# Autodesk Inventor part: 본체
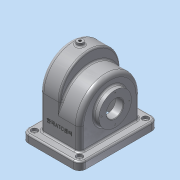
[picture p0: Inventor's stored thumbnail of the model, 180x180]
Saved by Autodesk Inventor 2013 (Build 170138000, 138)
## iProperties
Created: 2017-11
Part Number: 본체
Material: 알루미늄 6061
Document SubType Name: Modeling
Designer: dgall
Density: 2.71 g/cm^3
Mass: 1079.37 g
Surface Area: 1182.18 cm^2
Volume: 398.29 cm^3
Author: dgall
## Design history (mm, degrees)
sketch "스케치1"
  geometry: L1 (-38, -58)-(38, -58); L2 (38, -58)-(38, 58); L3 (38, 58)-(-38, 58); L4 (-38, 58)-(-38, -58); L5 (-38, -58)-(38, 58); L6 (38, -58)-(-38, 58); 1 further point
  constraints: 12 end point, 2 midpoint, 2 parallel, 1 horizontal, 1 perpendicular
  dimensions: "d0" = 76 distance of L3.end L2.end; "d1" = 116 distance between parallel lines of L1 L3
extrude "돌출1" new body sketch "스케치1" distance "d2" = 138; taper "d3" = 0 deg
node "작업 평면1"
sketch "스케치2"
  geometry: L1 (-58, 0)-(-58, 138) reference; L2 (58, 0)-(58, 138) reference; L3 (58, 0)-(-58, 0) reference; L4 (58, 138)-(-58, 138) reference; L5 (-58, 57)-(-58, 138); L6 (58, 138)-(-58, 138); L7 (58, 138)-(58, 57); A1 r 58 centre (0, 57) between (58, 57) and (-58, 57); 1 further point
  constraints: 6 end point, 2 collinear, 2 point on circle, 2 point on line, 1 centre point, 1 perpendicular, 1 vertical alignment
  dimensions: "d5" = 57 distance of point (0, 0) A1.centre; "d6" = 116 diameter of A1
extrude "돌출2" cut sketch "스케치2" stored distance "d7" = 138; taper "d8" = 0 deg
fillet "모깎기1" dims "d9" = 58
feature "쉘3" dims "d19" = 5
fillet "모깎기5" dims "d21" = 8
fillet "모깎기6" dims "d22" = 3
fillet "모깎기7" dims "d23" = 3
sketch "스케치4"
  geometry: L1 (0, 0)-(0, 100) reference; C1 r 31 at (-65, 50); 2 further points
  constraints: 1 centre point, 1 horizontal alignment, 1 midpoint
  dimensions: "d25" = 62 diameter of C1; "d27" = 65 distance of C1.centre point (0, 50)
extrude "돌출3" join sketch "스케치4" distance "d28" = 10; taper "d29" = 0 deg
sketch "스케치5"
  geometry: C1 r 31 at (0, 0) reference; C2 r 16 at (0, 0); 1 further point
  constraints: 1 centre point, 1 coincident
  dimensions: "d30" = 32 diameter of C2
extrude "돌출4" cut sketch "스케치5" stored distance "d32" = 10; taper "d33" = 0 deg
sketch "스케치6"
  geometry: C1 r 16 at (65, 50) reference; C2 r 37.5 at (65, 50); 1 further point
  constraints: 1 centre point, 1 coincident
  dimensions: "d34" = 75 diameter of C2
extrude "돌출5" join sketch "스케치6" distance "d35" = 9; taper "d36" = 0 deg
chamfer "모따기1" distance "d37" = 1; stored, may be unused: second distance "d38" = 2, angle "d39" = 45 deg
fillet "모깎기8" dims "d40" = 3
node "작업 평면8"
sketch "스케치7"
  geometry: L1 (-38, -50)-(-38, 50) reference; C1 r 6 at (-19, 0); 1 further point
  constraints: 1 centre point, 1 horizontal alignment
  dimensions: "d42" = 12 diameter of C1; "d44" = 19 distance from line of L1 C1.centre
extrude "돌출6" join sketch "스케치7" stored distance "d45" = 12 (= d42); taper "d46" = 0 deg
sketch "스케치8"
  geometry: C1 r 6 at (0, 0) reference; C2 r 2.5 at (0, 0); 1 further point
  constraints: 1 centre point, 1 coincident
  dimensions: "d47" = 5 diameter of C2
extrude "돌출7" cut sketch "스케치8" stored distance "d48" = 9; taper "d49" = 0 deg
feature "스레드1" dims "d50" = 10, "d51" = 0
fillet "모깎기9" dims "d52" = 3
sketch "스케치9"
  geometry: L1 (-38, -50)-(-38, 50) reference; L2 (30, -58)-(-30, -58) reference; L3 (38, 50)-(38, -50) reference; L4 (-30, 58)-(30, 58) reference; L5 (-55, -75)-(55, -75); L6 (55, -75)-(55, 75); L7 (55, 75)-(-55, 75); L8 (-55, 75)-(-55, -75); L9 (-55, -75)-(55, 75); L10 (55, -75)-(-55, 75); A1 r 8 centre (-30, 50) between (-30, 58) and (-38, 50) reference; A2 r 8 centre (-30, -50) between (-38, -50) and (-30, -58) reference; A3 r 8 centre (30, -50) between (30, -58) and (38, -50) reference; A4 r 8 centre (30, 50) between (38, 50) and (30, 58) reference; 1 further point
  constraints: 12 end point, 2 midpoint, 2 parallel, 1 horizontal, 1 perpendicular
  dimensions: "d53" = 110 distance of L7.end L6.end; "d54" = 150 distance of L6.end L5.end
extrude "돌출8" join sketch "스케치9" distance "d55" = 15; taper "d56" = 0 deg
fillet "모깎기10" dims "d57" = 12
fillet "모깎기11" dims "d58" = 3
fillet "모깎기12" dims "d59" = 3
sketch "스케치10"
  geometry: C1 r 2.5 at (43, -63); C2 r 2.5 at (43, 63); C3 r 2.5 at (-43, 63); C4 r 2.5 at (-43, -63); A1 r 9 centre (43, 63) between (52, 63) and (43, 72) reference; A2 r 9 centre (-43, 63) between (-43, 72) and (-52, 63) reference; A3 r 9 centre (-43, -63) between (-52, -63) and (-43, -72) reference; A4 r 9 centre (43, -63) between (43, -72) and (52, -63) reference; 1 further point
  constraints: 4 centre point, 4 coincident, 3 equal radius
  dimensions: "d61" = 5 diameter of C1
extrude "돌출9" cut sketch "스케치10" stored distance "d63" = 15; taper "d64" = 0 deg
sketch "스케치11"
  geometry: C1 r 2.5 at (-43, 63) reference; C2 r 2.5 at (43, -63) reference; C3 r 2.5 at (43, 63) reference; C4 r 2.5 at (-43, -63) reference; C5 r 6 at (43, -63); C6 r 6 at (43, 63); C7 r 6 at (-43, 63); C8 r 6 at (-43, -63); A1 r 9 centre (43, 63) between (52, 63) and (43, 72) reference; A2 r 9 centre (-43, 63) between (-43, 72) and (-52, 63) reference; A3 r 9 centre (-43, -63) between (-52, -63) and (-43, -72) reference; A4 r 9 centre (43, -63) between (43, -72) and (52, -63) reference; 1 further point
  constraints: 4 centre point, 4 coincident, 1 equal radius
  dimensions: "d65" = 12 diameter of C5; "d66" = 12 diameter of C7; "d67" = 12 diameter of C8
extrude "돌출10" cut sketch "스케치11" distance "d68" = 5; taper "d69" = 0 deg
sketch "스케치12" dims "d70" = 52
  geometry: C1 r 17 at (0, 0) reference; 3 further points
  constraints: 2 horizontal alignment, 1 coincident, 2 other
hole "구멍1" sketch "스케치12" at (-26, 0) diameter "d71" = 2.459; stored, may be unused: countersink angle "d75" = 90 deg, drill point angle "d77" = 118 deg; dims "d72" = 6, "d73" = 4, "d74" = 2, "d76" = 8
sketch "스케치13" dims "d81" = 58
  geometry: C1 r 37.5 at (0, 0) reference; C2 r 17 at (0, 0) reference; 3 further points
  constraints: 2 horizontal alignment, 1 coincident, 2 other
hole "구멍2" sketch "스케치13" at (29, 0) diameter "d82" = 2.459; stored, may be unused: countersink angle "d86" = 90 deg, drill point angle "d88" = 118 deg; dims "d83" = 6, "d84" = 4, "d85" = 2, "d87" = 8
sketch "스케치14"
  geometry: L1 (-25.145, -1.938)-(31.145, -1.938); L2 (31.145, -1.938)-(31.145, -32.062); L3 (31.145, -32.062)-(-25.145, -32.062); L4 (-25.145, -32.062)-(-25.145, -1.938); L5 (3, -1.938)-(3, -32.062); L6 (-25.145, -17)-(31.145, -17); L7 (46, -57)-(-40, -57) reference; L8 (-35, 23)-(-35, -39) reference; 1 further point
  constraints: 4 end point, 4 midpoint, 2 other
  dimensions: "d92" = 40 distance between parallel lines of L7 L6; "d93" = 38 distance between parallel lines of L8 L5
feature "엠보싱1" sketch "스케치14" dims "d0" = 76, "d1" = 116, "d94" = 0.5, "d95" = 0
node "솔리드1"
pattern_circular "원형 패턴1" dims angle "d79" = 360 deg
pattern_circular "원형 패턴2" dims angle "d90" = 360 deg
other parameters: "d4" = 0, "d41" = 144
